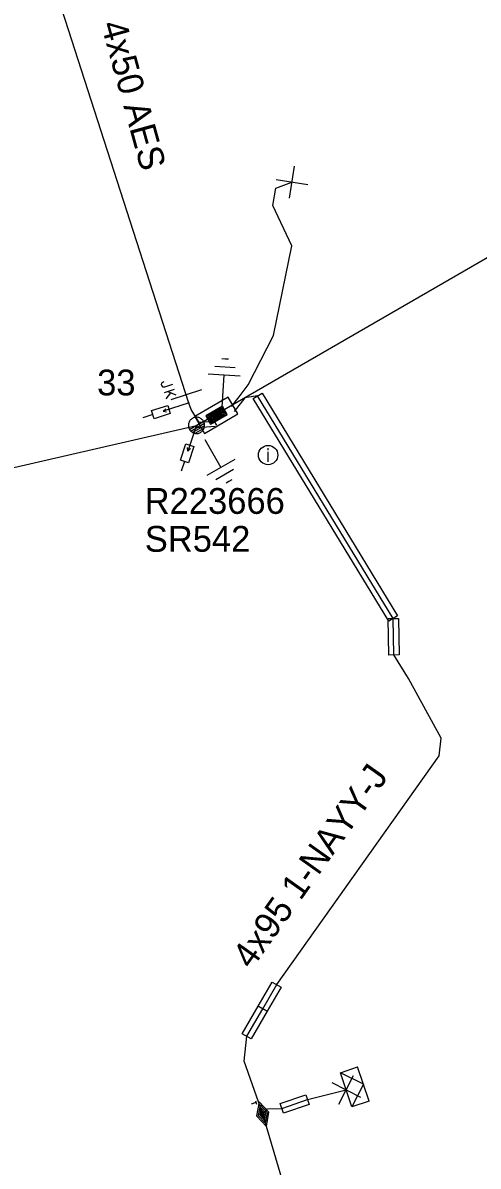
# Model space of a CAD drawing. Extents: x -536148 to -535465, y -1201639 to -1201298.
# Drawn here: x -535546.95 to -535529.32, y -1201567.67 to -1201523.39 of the extents above; entities that cross this region are included whole.
import ezdxf

# ---------------------------------------------------------------- set-up
doc = ezdxf.new("R2010")
doc.units = 0
for name, color, linetype in [('CIZÍ_NADZEM_POPIS', 7, 'Continuous'), ('CIZÍ_PODZEM', 7, 'Continuous'), ('CIZÍ_PODZEM_POPIS', 7, 'Continuous'), ('DOPLŇ_POPISY', 7, 'Continuous'), ('ELE_EON', 7, 'Continuous'), ('ELE_EON_POPIS', 7, 'Continuous'), ('KN_HRAN_PARCEL_NEVIDITELNÁ', 7, 'Continuous'), ('KN_HRAN_PODZEM', 7, 'Continuous'), ('KN_HRAN_POHYBLIVÁ', 7, 'Continuous'), ('KN_HRAN_STÁTNÍ', 7, 'Continuous'), ('KN_VKP_HRAN_', 7, 'Continuous'), ('KN_VKP_HRAN_NEZNATELNÁ', 7, 'Continuous'), ('KN_VKP_HRAN_PARCEL_NEVIDITELNÁ', 7, 'Continuous'), ('KN_VKP_HRAN_SPORNÁ', 7, 'Continuous'), ('NADZEM_NN_IZOL_POPIS', 7, 'Continuous'), ('OP KABELU NN', 7, 'Continuous'), ('PK_HRAN_POHYBLIVÁ', 7, 'Continuous'), ('PLG_EXPORT_GPE', 7, 'Continuous'), ('PODZEM_NN', 7, 'Continuous'), ('PODZEM_NN_POPIS', 7, 'Continuous'), ('PROJEKT', 7, 'Continuous'), ('RÁMEČEK', 7, 'Continuous'), ('SDEL_EON_POPIS', 7, 'Continuous'), ('ZRUŠENO', 7, 'Continuous')]:
    doc.layers.add(name, color=color, linetype=linetype)

# ---------------------------------------------------------------- blocks, each defined once
blk = doc.blocks.new('NN440')
at = {"layer": 'ELE_EON_POPIS'}
for points in [[(0.631, -0.004), (0.627, 0.062), (0.617, 0.127), (0.6, 0.191), (0.577, 0.252), (0.547, 0.311), (0.511, 0.366), (0.469, 0.417), (0.423, 0.464), (0.371, 0.505), (0.316, 0.542), (0.257, 0.571), (0.196, 0.595), (0.132, 0.612), (0.067, 0.622), (0.001, 0.626), (-0.065, 0.622), (-0.13, 0.612), (-0.194, 0.595), (-0.255, 0.571), (-0.314, 0.542), (-0.369, 0.505), (-0.42, 0.464), (-0.467, 0.417), (-0.509, 0.366), (-0.544, 0.311), (-0.574, 0.252), (-0.598, 0.191), (-0.615, 0.127), (-0.626, 0.062), (-0.629, -0.004), (-0.626, -0.07), (-0.615, -0.135), (-0.598, -0.199), (-0.574, -0.26), (-0.544, -0.319), (-0.509, -0.374), (-0.467, -0.426), (-0.42, -0.472), (-0.369, -0.514), (-0.314, -0.55), (-0.255, -0.58), (-0.194, -0.603), (-0.13, -0.62), (-0.065, -0.631), (0.001, -0.634), (0.067, -0.631), (0.132, -0.62), (0.196, -0.603), (0.257, -0.58), (0.316, -0.55), (0.371, -0.514), (0.423, -0.472), (0.469, -0.426), (0.511, -0.374), (0.547, -0.319), (0.577, -0.26), (0.6, -0.199), (0.617, -0.135), (0.627, -0.07), (0.631, -0.004)], [(-0.631, 0), (0.629, 0)], [(-0.601, -0.177), (0.57, -0.177)], [(-0.513, -0.325), (0.501, -0.325)], [(-0.375, -0.473), (0.353, -0.473)]]:
    blk.add_lwpolyline(points, dxfattribs=at)
blk = doc.blocks.new('NN840')
at = {"layer": 'RÁMEČEK'}
for points in [[(0.003, 0.619), (0.003, -0.631)], [(-0.538, -0.385), (-0.538, -0.71)], [(-0.332, -0.385), (-0.332, -0.798)], [(-0.332, -0.641), (-0.125, -0.385)], [(-0.745, -0.71), (-0.745, -0.66)], [(-0.73, -0.764), (-0.745, -0.71)], [(-0.657, -0.798), (-0.73, -0.764)], [(-0.627, -0.798), (-0.657, -0.798)], [(-0.558, -0.764), (-0.627, -0.798)], [(-0.538, -0.71), (-0.558, -0.764)], [(-0.263, -0.557), (-0.091, -0.798)]]:
    blk.add_lwpolyline(points, dxfattribs=at)
blk = doc.blocks.new('NN770')
at = {"layer": 'CIZÍ_PODZEM_POPIS'}
for p, q in [((0.002, 0.187), (0.002, 0.263)), ((0.002, -0.276), (0.002, 0.111))]:
    blk.add_line(p, q, dxfattribs=at)
blk.add_circle((0, -0.008), 0.375, dxfattribs=at)
blk = doc.blocks.new('NN880')
at = {"layer": 'SDEL_EON_POPIS'}
for points in [[(0.001, 0.248), (-0.499, 0)], [(0.001, 0.185), (-0.373, 0)], [(0.001, 0.122), (-0.247, 0)], [(0.001, 0.059), (-0.125, 0)], [(0.501, 0), (0.001, 0.248)], [(0.375, 0), (0.001, 0.185)], [(0.249, 0), (0.001, 0.122)], [(0.127, 0), (0.001, 0.059)], [(-0.566, -0.13), (-0.436, -0.13)], [(-0.499, 0), (0.001, -0.252)], [(-0.499, -0.13), (-0.499, -0.327)], [(-0.373, 0), (0.001, -0.189)], [(-0.247, 0), (0.001, -0.126)], [(-0.125, 0), (0.001, -0.063)], [(0.001, -0.252), (0.501, 0)], [(0.001, -0.189), (0.375, 0)], [(0.001, -0.126), (0.249, 0)], [(0.001, -0.063), (0.127, 0)]]:
    blk.add_lwpolyline(points, dxfattribs=at)
blk = doc.blocks.new('NN800')
at = {"layer": 'ELE_EON'}
for points in [[(-0.442, 0.442), (0.442, -0.442)], [(-0.442, -0.442), (0.442, 0.442)]]:
    blk.add_lwpolyline(points, dxfattribs=at)
blk = doc.blocks.new('NN820')
at = {"layer": 'DOPLŇ_POPISY'}
for points in [[(-0.003, 0.004), (-0.003, -1.049)], [(-0.165, -0.813), (0.165, -0.813)], [(-0.165, -1.473), (-0.165, -0.813)], [(0.165, -0.813), (0.165, -1.473)], [(-0.003, -1.049), (-0.062, -0.926)], [(-0.003, -1.049), (0.057, -0.926)], [(0.165, -1.473), (-0.165, -1.473)], [(-0.003, -1.473), (-0.003, -1.871)]]:
    blk.add_lwpolyline(points, dxfattribs=at)
blk = doc.blocks.new('NN620')
at = {"layer": 'CIZÍ_NADZEM_POPIS'}
for points in [[(0.752, 0.004), (-0.748, 0.004)], [(-0.748, 0.004), (-0.748, -0.746)], [(0.752, -0.746), (0.752, 0.004)], [(0.368, -0.18), (-0.376, -0.18)], [(-0.376, -0.18), (-0.376, -0.558)], [(0.321, -0.227), (-0.329, -0.227)], [(-0.329, -0.227), (-0.329, -0.51)], [(0.274, -0.274), (-0.281, -0.274)], [(-0.281, -0.274), (-0.281, -0.463)], [(0.227, -0.321), (-0.234, -0.321)], [(-0.234, -0.321), (-0.234, -0.416)], [(-0.234, -0.416), (0.227, -0.416)], [(-0.193, -0.369), (0.185, -0.369)], [(0.227, -0.416), (0.227, -0.321)], [(0.274, -0.463), (0.274, -0.274)], [(0.321, -0.51), (0.321, -0.227)], [(0.368, -0.558), (0.368, -0.18)], [(-0.748, -0.746), (0.752, -0.746)], [(-0.376, -0.558), (0.368, -0.558)], [(-0.329, -0.51), (0.321, -0.51)], [(-0.281, -0.463), (0.274, -0.463)]]:
    blk.add_lwpolyline(points, dxfattribs=at)
blk = doc.blocks.new('NN630')
at = {"layer": 'CIZÍ_PODZEM'}
for points in [[(-0.003, -0.7), (-0.703, 0)], [(-0.703, -0.7), (-0.703, 0), (0.697, 0), (0.697, -0.7)], [(-0.003, -0.7), (0.697, 0)], [(-0.703, -0.7), (0.697, -0.7)]]:
    blk.add_lwpolyline(points, dxfattribs=at)
blk = doc.blocks.new('NN810')
at = {"layer": 'PLG_EXPORT_GPE'}
for points in [[(0.004, -0.64), (0.004, -1.89)], [(0.629, -1.89), (-0.621, -1.89)], [(0.388, -2.2), (-0.399, -2.2)], [(0.004, -2.515), (-0.124, -2.515)], [(0.137, -2.515), (0.004, -2.515)]]:
    blk.add_lwpolyline(points, dxfattribs=at)

msp = doc.modelspace()

# ---------------------------------------------------------------- linework, layer by layer
at = {"layer": 'ELE_EON'}
for points in [[(-535540.23, -1201538.98), (-535514.019, -1201523.838), (-535479.236, -1201502.472), (-535465.278, -1201493.607)], [(-535561.176, -1201543.795), (-535540.23, -1201538.98)]]:
    msp.add_lwpolyline(points, dxfattribs=at)
at = {"layer": 'KN_HRAN_PARCEL_NEVIDITELNÁ'}
for points in [[(-535537.689, -1201537.736), (-535532.439, -1201546.356), (-535532.781, -1201546.564), (-535538.031, -1201537.944)], [(-535532.41, -1201546.456), (-535532.38, -1201547.866), (-535532.78, -1201547.874), (-535532.81, -1201546.464)], [(-535536.947, -1201560.74), (-535537.487, -1201561.67), (-535537.833, -1201561.47), (-535537.293, -1201560.54)], [(-535538.453, -1201562.54), (-535537.833, -1201561.47), (-535537.487, -1201561.67), (-535538.107, -1201562.74)], [(-535536.985, -1201565.241), (-535535.995, -1201564.901), (-535535.865, -1201565.279), (-535536.855, -1201565.619)]]:
    msp.add_lwpolyline(points, close=True, dxfattribs=at)
at = {"layer": 'NADZEM_NN_IZOL_POPIS'}
msp.add_lwpolyline([(-535540.439, -1201538.364), (-535540.519, -1201538.116), (-535547.83, -1201515.436), (-535551.375, -1201509.636), (-535552.066, -1201508.681), (-535553.538, -1201506.643), (-535563.322, -1201493.118), (-535566.21, -1201489.133)], dxfattribs=at)
at = {"layer": 'PODZEM_NN_POPIS'}
for points in [[(-535538.872, -1201538.248), (-535538.578, -1201537.878), (-535538.228, -1201537.41), (-535537.25, -1201535.5), (-535536.54, -1201532.03), (-535537.27, -1201530.46), (-535537.16, -1201529.79), (-535536.53, -1201529.56)], [(-535537.66, -1201565.65), (-535537.48, -1201565.45), (-535536.92, -1201565.43), (-535535.93, -1201565.09), (-535534.43, -1201564.71)]]:
    msp.add_lwpolyline(points, dxfattribs=at)
at = {"layer": 'PROJEKT'}
for points in [[(-535535.21, -1201573.95), (-535537.66, -1201565.65), (-535538.38, -1201563.6), (-535538.28, -1201562.64), (-535537.66, -1201561.57), (-535537.12, -1201560.64), (-535530.83, -1201551.78), (-535530.75, -1201551.1), (-535532.02, -1201548.79), (-535532.58, -1201547.87), (-535532.61, -1201546.46), (-535537.86, -1201537.84), (-535538.354, -1201537.917), (-535538.774, -1201538.446)], [(-535539.437, -1201538.974), (-535539.525, -1201538.828), (-535540.129, -1201538.872), (-535540.439, -1201538.364)], [(-535539.505, -1201539.027), (-535540.173, -1201539.076), (-535540.23, -1201538.98)]]:
    msp.add_lwpolyline(points, dxfattribs=at)

# ---------------------------------------------------------------- block references
at = {"layer": 'DOPLŇ_POPISY', "xscale": 0.5000000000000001, "yscale": 0.4999999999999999, "rotation": 29.96083386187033}
msp.add_blockref('NN440', (-535540.23, -1201538.98), dxfattribs=at)
at = {"layer": 'KN_HRAN_PODZEM', "rotation": -73.5544154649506}
msp.add_blockref('NN880', (-535537.66, -1201565.65), dxfattribs=at)
at = {"layer": 'KN_HRAN_POHYBLIVÁ', "rotation": -72.13095977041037}
msp.add_blockref('NN840', (-535540.622, -1201537.795), dxfattribs=at)
at = {"layer": 'KN_HRAN_STÁTNÍ'}
for p, rotation in [((-535540.519, -1201538.116), -72.13095968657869), ((-535540.23, -1201538.98), -18.24602869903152)]:
    msp.add_blockref('NN820', p, dxfattribs=dict(at, rotation=rotation))
at = {"layer": 'KN_VKP_HRAN_NEZNATELNÁ'}
for p, rotation in [((-535536.53, -1201529.56), 36.095597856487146), ((-535534.43, -1201564.71), 18.117972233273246)]:
    msp.add_blockref('NN800', p, dxfattribs=dict(at, rotation=rotation))
at = {"layer": 'KN_VKP_HRAN_SPORNÁ', "rotation": 108.5283246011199}
msp.add_blockref('NN630', (-535534.43, -1201564.71), dxfattribs=at)
at = {"layer": 'OP KABELU NN', "rotation": -149.77816187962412}
msp.add_blockref('NN620', (-535539.27, -1201538.91), dxfattribs=at)
at = {"layer": 'PK_HRAN_POHYBLIVÁ'}
msp.add_blockref('NN770', (-535537.453, -1201540.122), dxfattribs=at)
at = {"layer": 'RÁMEČEK'}
for p, rotation in [((-535539.27, -1201538.91), 176.4442276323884), ((-535540.23, -1201538.98), 29.96083386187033)]:
    msp.add_blockref('NN810', p, dxfattribs=dict(at, rotation=rotation))

# ---------------------------------------------------------------- texts
at = {"layer": 'KN_VKP_HRAN_'}
msp.add_text('SR542', height=1, dxfattribs=at).set_placement((-535542.23, -1201543.876))
at = {"layer": 'KN_VKP_HRAN_PARCEL_NEVIDITELNÁ'}
msp.add_text('R223666', height=1, dxfattribs=at).set_placement((-535542.234, -1201542.408))
at = {"layer": 'PLG_EXPORT_GPE'}
msp.add_text('33', height=1, dxfattribs=at).set_placement((-535544.077, -1201537.821))
at = {"layer": 'PODZEM_NN'}
msp.add_text('4x50 AES', height=1, rotation=285.401, dxfattribs=at).set_placement((-535543.936, -1201523.451))
at = {"layer": 'ZRUŠENO'}
msp.add_text('4x95 1-NAYY-J', height=1, rotation=54.628, dxfattribs=at).set_placement((-535538.096, -1201560.083))

doc.saveas('drawing.dxf')
